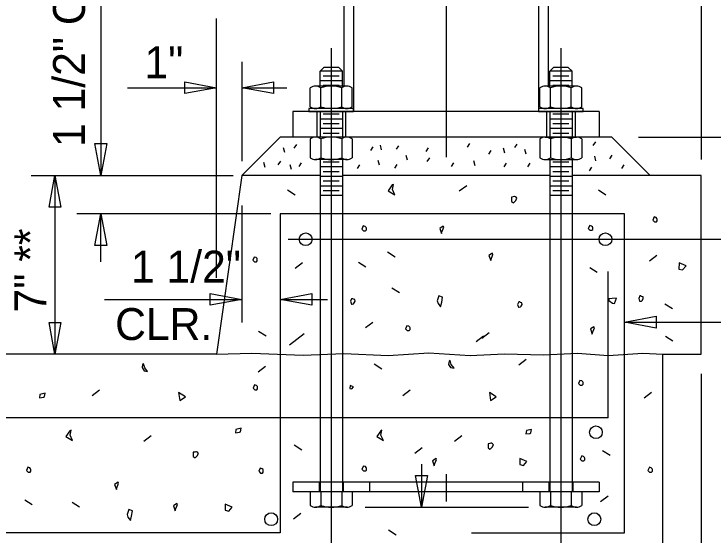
# Model space of a CAD drawing. Extents: x 0 to 45.3, y 0 to 31.4.
# Drawn here: x 34.65 to 39.216, y 7.306 to 10.708 of the extents above; entities that cross this region are included whole.
import ezdxf

# ---------------------------------------------------------------- set-up
doc = ezdxf.new("R2010")
doc.units = 0
for name, color, linetype in [('BRDG_ANNO_General-Notes', 7, 'Continuous'), ('BRDG_BASE_Dtlctrln', 7, 'Continuous'), ('BRDG_BASE_Hidden-Line', 7, 'Continuous'), ('BRDG_BASE_Obj-Line', 7, 'Continuous'), ('BRDG_BASE_Pattern', 7, 'Continuous'), ('BRDG_BASE_Phtline', 7, 'Continuous'), ('BRDG_BASE_Rebar', 7, 'Continuous'), ('Default', 7, 'Continuous')]:
    doc.layers.add(name, color=color, linetype=linetype)

# ---------------------------------------------------------------- blocks, each defined once
blk = doc.blocks.new('TERM')
at = {"layer": 'Default'}
for p, q in [((-1.6, -0.267), (-1.6, 0.267)), ((-1.6, 0.267), (0, 0)), ((0, 0), (-1.6, -0.267))]:
    blk.add_line(p, q, dxfattribs=at)

msp = doc.modelspace()

# ---------------------------------------------------------------- linework, layer by layer
at = {"layer": 'BRDG_ANNO_General-Notes'}
for p, q in [((39.139, 11.9524), (39.139, 9.7586)), ((35.2178, 11.0432), (35.2178, 9.6537)), ((35.9724, 8.9856), (35.9724, 10.6789)), ((36.139, 10.3965), (36.139, 9.7476)), ((35.7657, 10.1881), (35.7657, 10.2656)), ((35.7657, 10.2656), (35.9724, 10.2268)), ((36.139, 10.2268), (36.3457, 10.2656)), ((36.3457, 10.2656), (36.3457, 10.1881)), ((35.3911, 10.2268), (35.9724, 10.2268)), ((35.9724, 10.2268), (35.7657, 10.1881)), ((36.139, 10.2268), (36.4322, 10.2268)), ((36.3457, 10.1881), (36.139, 10.2268)), ((38.7295, 9.9037), (40.0995, 9.9037)), ((34.7616, 9.6537), (36.0824, 9.6537)), ((34.8791, 9.4471), (34.9178, 9.6537)), ((34.9178, 9.6537), (34.9178, 8.4871)), ((34.9178, 9.6537), (34.9566, 9.4471)), ((36.139, 9.4565), (36.139, 8.6944)), ((34.9566, 9.4471), (34.8791, 9.4471)), ((36.3274, 9.4037), (35.0615, 9.4037)), ((35.2178, 9.0903), (35.2178, 9.4037)), ((35.9324, 8.8058), (35.9324, 8.8833)), ((35.9324, 8.8833), (36.139, 8.8445)), ((36.389, 8.8445), (36.5957, 8.8833)), ((36.5957, 8.8833), (36.5957, 8.8058)), ((35.2419, 8.8445), (36.139, 8.8445)), ((36.139, 8.8445), (35.9324, 8.8058)), ((36.389, 8.8445), (36.697, 8.8445)), ((36.5957, 8.8058), (36.389, 8.8445)), ((38.639, 8.6953), (38.8457, 8.734)), ((38.8457, 8.734), (38.8457, 8.6565)), ((34.8791, 8.6937), (34.9566, 8.6937)), ((34.9178, 8.4871), (34.8791, 8.6937)), ((34.9566, 8.6937), (34.9178, 8.4871)), ((38.639, 8.6953), (42.5068, 8.6953)), ((38.8457, 8.6565), (38.639, 8.6953)), ((39.1391, 8.3592), (39.1391, 5.6928)), ((37.3117, 7.769), (37.3117, 7.4871)), ((37.273, 7.6937), (37.3505, 7.6937)), ((37.3117, 7.4871), (37.273, 7.6937)), ((37.3505, 7.6937), (37.3117, 7.4871)), ((36.9434, 7.4871), (38.011, 7.4871))]:
    msp.add_line(p, q, dxfattribs=at)
at = {"layer": 'BRDG_BASE_Dtlctrln'}
for p, q in [((37.4724, 13.6611), (37.4724, 9.7726)), ((36.7224, 10.4858), (36.7224, 5.6617)), ((38.2224, 10.4858), (38.2224, 5.6617)), ((36.442, 9.2371), (41.0105, 9.2371)), ((37.4724, 7.7025), (37.4724, 7.524))]:
    msp.add_line(p, q, dxfattribs=at)
at = {"layer": 'BRDG_BASE_Hidden-Line'}
for p, q in [((36.6286, 10.0704), (36.6286, 9.9037)), ((36.6494, 10.0704), (36.6494, 9.9037)), ((36.7744, 10.053), (36.6703, 10.053)), ((36.7953, 10.0704), (36.7953, 9.9037)), ((36.8161, 10.0704), (36.8161, 9.9037)), ((38.1286, 10.0704), (38.1286, 9.9037)), ((38.1494, 10.0704), (38.1494, 9.9037)), ((38.2744, 10.053), (38.1703, 10.053)), ((38.2953, 10.0704), (38.2953, 9.9037)), ((38.3161, 10.0704), (38.3161, 9.9037)), ((36.7953, 10.0218), (36.6494, 10.0218)), ((38.2953, 10.0218), (38.1494, 10.0218)), ((36.7953, 9.9593), (36.6494, 9.9593)), ((36.7744, 9.9905), (36.6703, 9.9905)), ((38.2953, 9.9593), (38.1494, 9.9593)), ((38.2744, 9.9905), (38.1703, 9.9905)), ((36.7744, 9.928), (36.6703, 9.928)), ((38.2744, 9.928), (38.1703, 9.928)), ((36.6442, 7.6498), (36.6442, 7.5873)), ((36.6494, 7.6498), (36.6494, 7.5873)), ((36.7953, 7.6498), (36.7953, 7.5873)), ((36.8005, 7.6498), (36.8005, 7.5873)), ((36.9724, 7.6498), (36.9724, 7.5873)), ((37.9724, 7.6498), (37.9724, 7.5873)), ((38.1442, 7.6498), (38.1442, 7.5873)), ((38.1494, 7.6498), (38.1494, 7.5873)), ((38.2953, 7.6498), (38.2953, 7.5873)), ((38.3005, 7.6498), (38.3005, 7.5873))]:
    msp.add_line(p, q, dxfattribs=at)
at = {"layer": 'BRDG_BASE_Obj-Line'}
for p, q in [((36.8057, 13.9037), (36.8057, 10.2371)), ((36.8682, 13.8881), (36.8682, 10.0704)), ((38.0765, 13.586), (38.0765, 10.0704)), ((38.139, 13.5704), (38.139, 10.2405)), ((36.6737, 10.3586), (36.6494, 10.3343)), ((36.6494, 10.2371), (36.6494, 10.3343)), ((36.7953, 10.3343), (36.6494, 10.3343)), ((36.771, 10.3586), (36.6737, 10.3586)), ((36.7953, 10.3343), (36.771, 10.3586)), ((36.7953, 10.2371), (36.7953, 10.3343)), ((38.1737, 10.3586), (38.1494, 10.3343)), ((38.1494, 10.2371), (38.1494, 10.3343)), ((38.2953, 10.3343), (38.1494, 10.3343)), ((38.271, 10.3586), (38.1737, 10.3586)), ((38.2953, 10.3343), (38.271, 10.3586)), ((38.2953, 10.2371), (38.2953, 10.3343)), ((36.7744, 10.303), (36.6703, 10.303)), ((38.2744, 10.303), (38.1703, 10.303)), ((36.7224, 10.2371), (36.6207, 10.2371)), ((36.7953, 10.2718), (36.6494, 10.2718)), ((36.7744, 10.2405), (36.6703, 10.2405)), ((36.824, 10.2371), (36.7224, 10.2371)), ((38.2224, 10.2371), (38.1207, 10.2371)), ((38.2953, 10.2718), (38.1494, 10.2718)), ((38.2744, 10.2405), (38.1703, 10.2405)), ((38.324, 10.2371), (38.2224, 10.2371)), ((36.5857, 10.1021), (36.5857, 10.2262)), ((36.654, 10.1021), (36.654, 10.2262)), ((36.7908, 10.1021), (36.7908, 10.2262)), ((36.859, 10.1021), (36.859, 10.2262)), ((38.0857, 10.1021), (38.0857, 10.2262)), ((38.154, 10.1021), (38.154, 10.2262)), ((38.2908, 10.1021), (38.2908, 10.2262)), ((38.359, 10.1021), (38.359, 10.2262)), ((38.4724, 10.0704), (36.4724, 10.0704)), ((36.4724, 10.0704), (36.4724, 9.9037)), ((36.7224, 10.0912), (36.6207, 10.0912)), ((36.824, 10.0912), (36.7224, 10.0912)), ((38.2224, 10.0912), (38.1207, 10.0912)), ((38.324, 10.0912), (38.2224, 10.0912)), ((38.4724, 10.0704), (38.4724, 9.9037)), ((36.139, 9.6537), (36.389, 9.9037)), ((38.5557, 9.9037), (36.389, 9.9037)), ((36.5857, 9.8929), (36.5857, 9.7687)), ((36.7224, 9.9037), (36.6207, 9.9037)), ((36.654, 9.8929), (36.654, 9.7687)), ((36.8241, 9.9037), (36.7224, 9.9037)), ((36.7907, 9.8929), (36.7907, 9.7687)), ((36.8591, 9.8929), (36.8591, 9.7687)), ((38.0857, 9.8929), (38.0857, 9.7687)), ((38.1207, 9.9037), (38.2224, 9.9037)), ((38.154, 9.8929), (38.154, 9.7687)), ((38.2224, 9.9037), (38.3241, 9.9037)), ((38.2907, 9.8929), (38.2907, 9.7687)), ((38.3591, 9.8929), (38.3591, 9.7687)), ((38.8057, 9.6537), (38.5557, 9.9037)), ((36.7224, 9.7579), (36.6207, 9.7579)), ((36.6494, 9.7579), (36.6494, 7.6498)), ((36.7744, 9.7405), (36.6703, 9.7405)), ((36.8241, 9.7579), (36.7224, 9.7579)), ((36.7953, 9.7579), (36.7953, 7.6498)), ((38.1207, 9.7579), (38.2224, 9.7579)), ((38.1494, 9.7579), (38.1494, 7.6498)), ((38.2744, 9.7405), (38.1703, 9.7405)), ((38.2224, 9.7579), (38.3241, 9.7579)), ((38.2953, 9.7579), (38.2953, 7.6498)), ((36.7953, 9.7093), (36.6494, 9.7093)), ((38.2953, 9.7093), (38.1494, 9.7093)), ((36.139, 9.6537), (35.9724, 8.4871)), ((36.6494, 9.6537), (36.139, 9.6537)), ((36.7953, 9.6468), (36.6494, 9.6468)), ((36.7744, 9.678), (36.6703, 9.678)), ((38.1494, 9.6537), (36.7953, 9.6537)), ((38.2953, 9.6468), (38.1494, 9.6468)), ((38.2744, 9.678), (38.1703, 9.678)), ((39.139, 9.6537), (38.2953, 9.6537)), ((39.139, 8.4871), (39.139, 9.6537)), ((36.7744, 9.6155), (36.6703, 9.6155)), ((38.2744, 9.6155), (38.1703, 9.6155)), ((36.7953, 9.5843), (36.6494, 9.5843)), ((36.7744, 9.553), (36.6703, 9.553)), ((38.2953, 9.5843), (38.1494, 9.5843)), ((38.2744, 9.553), (38.1703, 9.553)), ((36.7953, 9.5218), (36.6494, 9.5218)), ((38.2953, 9.5218), (38.1494, 9.5218)), ((35.9724, 8.4871), (33.9307, 8.4871)), ((38.889, 7.1537), (38.889, 8.4871)), ((38.889, 8.4871), (39.139, 8.4871)), ((38.4724, 7.6498), (36.4724, 7.6498)), ((36.4724, 7.6498), (36.4724, 7.5873)), ((38.4724, 7.6498), (38.4724, 7.5873)), ((38.4724, 7.5873), (36.4724, 7.5873)), ((36.7224, 7.5873), (36.5857, 7.5873)), ((36.5857, 7.5873), (36.5857, 7.4979)), ((36.654, 7.5873), (36.654, 7.4979)), ((36.8591, 7.5873), (36.7224, 7.5873)), ((36.7907, 7.5873), (36.7907, 7.4979)), ((36.8591, 7.5873), (36.8591, 7.4979)), ((38.2224, 7.5873), (38.0857, 7.5873)), ((38.0857, 7.5873), (38.0857, 7.4979)), ((38.154, 7.5873), (38.154, 7.4979)), ((38.3591, 7.5873), (38.2224, 7.5873)), ((38.2907, 7.5873), (38.2907, 7.4979)), ((38.3591, 7.5873), (38.3591, 7.4979)), ((36.7224, 7.4871), (36.619, 7.4871)), ((36.8257, 7.4871), (36.7224, 7.4871)), ((38.2224, 7.4871), (38.119, 7.4871)), ((38.3257, 7.4871), (38.2224, 7.4871))]:
    msp.add_line(p, q, dxfattribs=at)
for points in [[(36.8682, 10.0704), (36.8682, 10.0912), (36.5765, 10.0912), (36.5765, 10.0704)], [(38.3682, 10.0704), (38.3682, 10.0912), (38.0765, 10.0912), (38.0765, 10.0704)]]:
    msp.add_lwpolyline(points, close=True, dxfattribs=at)
msp.add_lwpolyline([(35.9724, 8.4871), (36.2045, 8.4936), (36.5393, 8.4801), (36.8037, 8.491), (37.0954, 8.4787), (37.3599, 8.495), (37.6298, 8.4787), (37.8511, 8.4896), (38.1103, 8.4815), (38.3316, 8.4936), (38.5314, 8.4775), (38.7582, 8.4936), (38.889, 8.4871)], dxfattribs=at)
for centre, radius, start, end in [((36.6198, 10.1778), 0.0593, 54.7697, 125.2303), ((36.7224, 10.0162), 0.2208, 71.9685, 108.0315), ((36.8249, 10.1778), 0.0593, 54.7697, 125.2303), ((38.1198, 10.1778), 0.0593, 54.7697, 125.2303), ((38.2224, 10.0162), 0.2208, 71.9685, 108.0315), ((38.3249, 10.1778), 0.0593, 54.7697, 125.2303), ((36.6198, 10.1505), 0.0593, 234.7697, 305.2303), ((36.7224, 10.3121), 0.2208, 251.9685, 288.0316), ((36.8249, 10.1505), 0.0593, 234.7697, 305.2303), ((38.1198, 10.1505), 0.0593, 234.7697, 305.2303), ((38.2224, 10.3121), 0.2208, 251.9685, 288.0316), ((38.3249, 10.1505), 0.0593, 234.7697, 305.2303), ((36.6198, 9.8445), 0.0593, 54.7697, 125.2303), ((36.7224, 9.6829), 0.2208, 71.9685, 108.0315), ((36.8249, 9.8445), 0.0593, 54.7697, 125.2303), ((38.1198, 9.8445), 0.0593, 54.7697, 125.2303), ((38.2224, 9.6829), 0.2208, 71.9685, 108.0316), ((38.3249, 9.8445), 0.0593, 54.7697, 125.2303), ((36.6198, 9.8172), 0.0593, 234.7697, 305.2303), ((36.7224, 9.9788), 0.2208, 251.9685, 288.0316), ((36.8249, 9.8172), 0.0593, 234.7697, 305.2303), ((38.1198, 9.8172), 0.0593, 234.7697, 305.2303), ((38.2224, 9.9788), 0.2208, 251.9684, 288.0315), ((38.3249, 9.8172), 0.0593, 234.7697, 305.2303), ((36.6198, 7.5463), 0.0593, 234.7697, 305.2303), ((36.7224, 7.7079), 0.2208, 251.9685, 288.0316), ((36.8249, 7.5463), 0.0593, 234.7697, 305.2303), ((38.1198, 7.5463), 0.0593, 234.7697, 305.2303), ((38.2224, 7.7079), 0.2208, 251.9685, 288.0316), ((38.3249, 7.5463), 0.0593, 234.7697, 305.2303)]:
    msp.add_arc(centre, radius, start, end, dxfattribs=at)
at = {"layer": 'BRDG_BASE_Pattern'}
for p, q in [((36.4376, 9.5593), (36.487, 9.528)), ((37.6072, 9.5866), (37.559, 9.5499)), ((38.4677, 9.5593), (38.5173, 9.528)), ((37.0909, 9.1539), (37.1404, 9.1228)), ((36.8997, 9.0883), (36.9492, 9.0571)), ((38.8497, 9.13), (38.8016, 9.0934)), ((36.5357, 9.0835), (36.4876, 9.0469)), ((38.411, 9.0536), (38.4605, 9.0224)), ((37.119, 8.9202), (37.1685, 8.8888)), ((38.9024, 8.8159), (38.9518, 8.7846)), ((36.9935, 8.6941), (36.9454, 8.6575)), ((36.2469, 8.6372), (36.2964, 8.606)), ((36.5456, 8.6187), (36.4493, 8.5453)), ((37.7177, 8.6034), (37.6695, 8.5668)), ((37.7539, 8.6264), (37.7057, 8.5897)), ((38.9053, 8.6039), (38.9548, 8.5727)), ((37.9968, 8.4508), (37.9487, 8.4142)), ((36.2935, 8.4066), (36.2454, 8.3699)), ((37.0028, 8.4226), (37.0523, 8.3914)), ((35.2087, 8.2514), (35.1606, 8.2148)), ((37.2389, 8.2514), (37.1907, 8.2148)), ((38.8146, 8.2367), (38.7665, 8.2001)), ((35.5458, 7.9524), (35.4977, 7.9158)), ((37.5759, 7.9524), (37.5278, 7.9158)), ((36.4813, 7.8939), (36.5308, 7.8627)), ((37.3157, 7.8749), (37.2676, 7.8383)), ((38.4954, 7.8586), (38.545, 7.8275)), ((34.7199, 7.5359), (34.7693, 7.5047)), ((38.5306, 7.5591), (38.4825, 7.5225)), ((35.0296, 7.5198), (35.079, 7.4887)), ((36.5246, 7.4458), (36.4765, 7.4093)), ((37.0972, 7.3386), (37.1466, 7.3076))]:
    msp.add_line(p, q, dxfattribs=at)
for points in [[(37.1209, 9.5917), (37.0953, 9.5531), (37.1385, 9.5271), (37.1228, 9.5622), (37.1294, 9.5944)], [(37.9004, 9.5118), (37.9004, 9.4839), (37.913, 9.4749), (37.917, 9.4784), (37.9278, 9.4896), (37.9351, 9.5044), (37.9298, 9.5118), (37.9224, 9.5153), (37.9189, 9.5153), (37.9116, 9.5132)], [(38.8317, 9.3824), (38.8225, 9.3622), (38.8333, 9.3509), (38.8465, 9.3509), (38.8519, 9.3568), (38.8519, 9.3676), (38.8502, 9.3729), (38.8443, 9.3789)], [(36.9319, 9.324), (36.9227, 9.3037), (36.9335, 9.2925), (36.9467, 9.2925), (36.9522, 9.2983), (36.9522, 9.3092), (36.9503, 9.3145), (36.9447, 9.3204)], [(37.4314, 9.3077), (37.4427, 9.2745), (37.4427, 9.278), (37.4574, 9.3151), (37.4536, 9.3224)], [(38.4109, 9.3268), (38.4016, 9.3065), (38.4124, 9.2953), (38.4257, 9.2953), (38.4311, 9.3012), (38.4311, 9.3119), (38.4292, 9.3174), (38.4236, 9.3232)], [(37.7529, 9.1309), (37.7643, 9.0978), (37.7643, 9.1014), (37.779, 9.1383), (37.7753, 9.1457)], [(36.2194, 9.121), (36.2101, 9.1007), (36.2209, 9.0895), (36.2342, 9.0895), (36.2396, 9.0954), (36.2396, 9.1061), (36.2378, 9.1116), (36.232, 9.1174)], [(38.9957, 9.0823), (38.9939, 9.0427), (39.0178, 9.0371), (39.0408, 9.0639)], [(37.4256, 8.868), (37.4144, 8.8349), (37.4202, 8.8182), (37.4366, 8.7961), (37.4439, 8.8256), (37.4495, 8.8589)], [(38.7312, 8.8501), (38.737, 8.8316), (38.7424, 8.8316), (38.7499, 8.8335), (38.7553, 8.8389), (38.7606, 8.8501), (38.7591, 8.861), (38.7499, 8.863), (38.746, 8.8668), (38.7386, 8.8668)], [(36.8482, 8.8322), (36.8541, 8.8136), (36.8594, 8.8136), (36.8669, 8.8155), (36.8723, 8.8209), (36.8777, 8.8322), (36.8761, 8.843), (36.8669, 8.845), (36.8629, 8.8489), (36.8556, 8.8489)], [(37.9395, 8.8112), (37.9454, 8.7928), (37.9508, 8.7928), (37.9583, 8.7947), (37.9637, 8.8), (37.969, 8.8112), (37.9675, 8.8222), (37.9583, 8.8241), (37.9543, 8.828), (37.947, 8.828)], [(38.5575, 8.8491), (38.5354, 8.8472), (38.5354, 8.8361), (38.5593, 8.8197), (38.5724, 8.8178), (38.5853, 8.8528)], [(37.2169, 8.6723), (37.2076, 8.6521), (37.2184, 8.6409), (37.2317, 8.6409), (37.2372, 8.6467), (37.2372, 8.6575), (37.2353, 8.663), (37.2297, 8.6688)], [(38.4157, 8.6513), (38.427, 8.6182), (38.427, 8.6217), (38.4418, 8.6587), (38.4381, 8.6661)], [(35.4905, 8.4191), (35.4863, 8.3985), (35.5001, 8.3781), (35.5232, 8.3736), (35.5048, 8.398), (35.4969, 8.4233)], [(37.4924, 8.4402), (37.4884, 8.4196), (37.5022, 8.3992), (37.5251, 8.3947), (37.5068, 8.4191), (37.4989, 8.4444)], [(38.3474, 8.3153), (38.3381, 8.2951), (38.349, 8.2839), (38.3622, 8.2839), (38.3676, 8.2898), (38.3676, 8.3005), (38.3658, 8.3059), (38.36, 8.3118)], [(36.2214, 8.2858), (36.2121, 8.2656), (36.2229, 8.2544), (36.2361, 8.2544), (36.2416, 8.2603), (36.2416, 8.271), (36.2397, 8.2765), (36.2341, 8.2823)], [(36.8458, 8.2822), (36.845, 8.2624), (36.8569, 8.2596), (36.8683, 8.273)], [(34.8198, 8.2242), (34.816, 8.2022), (34.8418, 8.2058), (34.8491, 8.2095), (34.8529, 8.2316)], [(35.7254, 8.2368), (35.7329, 8.1851), (35.7699, 8.2074)], [(37.7556, 8.2368), (37.763, 8.1851), (37.8, 8.2074)], [(36.1003, 7.9952), (36.0966, 7.9732), (36.1224, 7.9769), (36.1298, 7.9805), (36.1334, 8.0026)], [(37.9976, 7.9878), (37.9939, 7.9658), (38.0197, 7.9695), (38.027, 7.9731), (38.0307, 7.9952)], [(35.0154, 7.987), (34.9896, 7.9484), (35.0329, 7.9225), (35.0171, 7.9576), (35.0237, 7.9897)], [(37.0454, 7.987), (37.0198, 7.9484), (37.063, 7.9225), (37.0473, 7.9576), (37.054, 7.9897)], [(37.7469, 7.9021), (37.7469, 7.8742), (37.7595, 7.8652), (37.7635, 7.8689), (37.7743, 7.88), (37.7816, 7.8948), (37.7763, 7.9021), (37.7689, 7.9056), (37.7654, 7.9056), (37.7581, 7.9036)], [(35.82, 7.8457), (35.82, 7.8178), (35.8327, 7.8089), (35.8365, 7.8125), (35.8473, 7.8236), (35.8548, 7.8384), (35.8494, 7.8457), (35.842, 7.8493), (35.8383, 7.8493), (35.8311, 7.8473)], [(38.3587, 7.8218), (38.3494, 7.8015), (38.3602, 7.7902), (38.3735, 7.7902), (38.3789, 7.7962), (38.3789, 7.8069), (38.377, 7.8122), (38.3714, 7.8182)], [(37.3846, 7.7911), (37.3959, 7.7578), (37.3959, 7.7614), (37.4106, 7.7984), (37.4069, 7.8057)], [(37.9552, 7.8048), (37.9534, 7.7652), (37.9774, 7.7597), (38.0003, 7.7864)], [(34.7403, 7.7482), (34.731, 7.728), (34.7419, 7.7168), (34.7551, 7.7168), (34.7605, 7.7227), (34.7605, 7.7334), (34.7587, 7.7389), (34.7529, 7.7447)], [(36.2582, 7.742), (36.249, 7.7217), (36.2598, 7.7104), (36.273, 7.7104), (36.2784, 7.7164), (36.2784, 7.7271), (36.2767, 7.7324), (36.2708, 7.7383)], [(36.9327, 7.7556), (36.9234, 7.7354), (36.9343, 7.7242), (36.9475, 7.7242), (36.9529, 7.7301), (36.9529, 7.7408), (36.951, 7.7462), (36.9454, 7.7521)], [(38.8005, 7.7482), (38.7912, 7.728), (38.8021, 7.7168), (38.8153, 7.7168), (38.8207, 7.7227), (38.8207, 7.7334), (38.819, 7.7389), (38.8131, 7.7447)], [(35.3075, 7.6361), (35.319, 7.6028), (35.319, 7.6065), (35.3337, 7.6434), (35.33, 7.6507)], [(35.6917, 7.4968), (35.703, 7.4636), (35.703, 7.4672), (35.7177, 7.5043), (35.714, 7.5116)], [(36.0304, 7.5068), (36.0286, 7.4672), (36.0525, 7.4617), (36.0756, 7.4884)], [(35.3997, 7.4719), (35.3885, 7.4388), (35.3941, 7.4222), (35.4107, 7.4), (35.4181, 7.4296), (35.4236, 7.4627)]]:
    msp.add_lwpolyline(points, close=True, dxfattribs=at)
at = {"layer": 'BRDG_BASE_Phtline'}
for p, q in [((38.4344, 9.8494), (38.4501, 9.8729)), ((36.4093, 9.837), (36.4172, 9.8057)), ((36.4809, 9.8315), (36.4967, 9.855)), ((36.9801, 9.8171), (36.9958, 9.8406)), ((37.0414, 9.8514), (37.0492, 9.8201)), ((37.1489, 9.8243), (37.1646, 9.8478)), ((37.3427, 9.8099), (37.3585, 9.8334)), ((37.6121, 9.8386), (37.6278, 9.8622)), ((37.8457, 9.8334), (37.8536, 9.8021)), ((37.9209, 9.8351), (37.9366, 9.8586)), ((37.9858, 9.8262), (37.9937, 9.7949)), ((37.2101, 9.7867), (37.218, 9.7554)), ((37.7521, 9.7919), (37.7678, 9.8155)), ((38.4418, 9.7795), (38.4497, 9.7482)), ((38.5422, 9.7632), (38.5579, 9.7867)), ((36.2801, 9.74), (36.288, 9.7087)), ((36.3768, 9.7236), (36.3925, 9.7472)), ((36.5132, 9.7129), (36.529, 9.7364)), ((37.027, 9.7543), (37.0349, 9.7231)), ((37.3499, 9.7452), (37.3657, 9.7687)), ((37.508, 9.7129), (37.5237, 9.7364)), ((37.6518, 9.7507), (37.6597, 9.7194)), ((37.8526, 9.7093), (37.8684, 9.7328)), ((38.0071, 9.7093), (38.0228, 9.7328)), ((36.4524, 9.7256), (36.4603, 9.6943)), ((36.8939, 9.6985), (36.9096, 9.722)), ((37.1381, 9.7021), (37.1538, 9.7256)), ((38.4093, 9.6841), (38.425, 9.7076)), ((38.6211, 9.6985), (38.6369, 9.722))]:
    msp.add_line(p, q, dxfattribs=at)
at = {"layer": 'BRDG_BASE_Rebar'}
for q in [(38.5305, 9.0255), (33.9307, 8.0704)]:
    msp.add_line((38.5305, 8.0704), q, dxfattribs=at)
msp.add_lwpolyline([(37.639, 7.3204), (38.639, 7.3204), (38.639, 9.4037), (36.389, 9.4037), (36.389, 7.3204), (34.389, 7.3204)], dxfattribs=at)
for centre in [(36.5557, 9.2371), (38.514, 9.2371), (38.4515, 7.9766), (36.33, 7.409), (38.4411, 7.409)]:
    msp.add_circle(centre, 0.0417, dxfattribs=at)

# ---------------------------------------------------------------- block references
at = {"layer": 'BRDG_ANNO_General-Notes', "xscale": 0.13020833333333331, "yscale": 0.146484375}
for p, rotation in [((35.2178, 9.6537), -90), ((35.2178, 9.4037), 90)]:
    msp.add_blockref('TERM', p, dxfattribs=dict(at, rotation=rotation))

# ---------------------------------------------------------------- texts
at = {"layer": 'BRDG_ANNO_General-Notes'}
for s, height, p in [('1 1/2" CLR.', 0.208333, (35.1136, 9.8391)), ('7" **', 0.20833, (34.861, 8.759))]:
    msp.add_text(s, height=height, rotation=90, dxfattribs=at).set_placement(p)
for s, p in [('1"', (35.5025, 10.2883)), ('1 1/2"', (35.4141, 8.954)), ('CLR.', (35.3107, 8.579))]:
    msp.add_text(s, height=0.20833, dxfattribs=at).set_placement(p)

doc.saveas('drawing.dxf')
